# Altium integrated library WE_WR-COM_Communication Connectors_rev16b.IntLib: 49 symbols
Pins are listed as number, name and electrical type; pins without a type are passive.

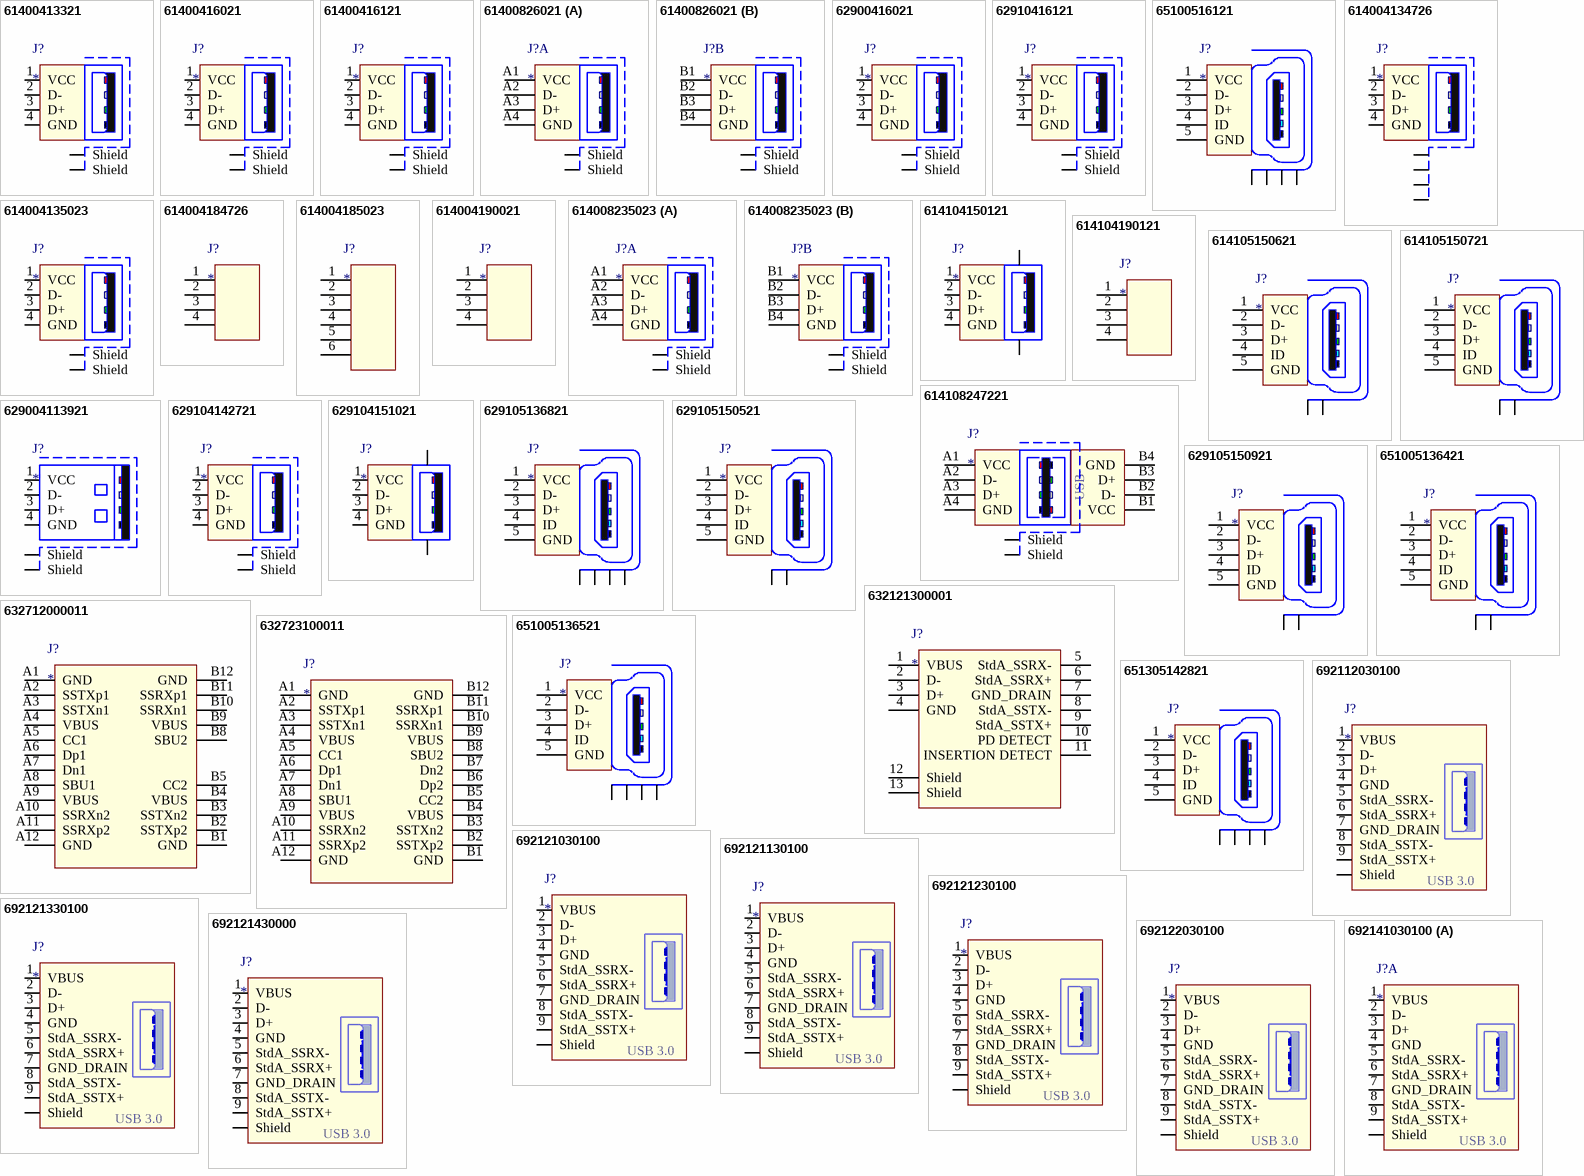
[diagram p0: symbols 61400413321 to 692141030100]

## 61400413321
designator J?
WR-COM USB Vertical Type B; Manufacturer: Würth Elektronik eiSos GmbH; partNo: 61400413321; ComponentLink1 Description: Manufacturer; ComponentLink2 Description: Datasheet; NoPins: 4
footprint 61400413321 (F Str 04p Btype vertical)
pins: 1 VCC, 2 D-, 3 D+, 4 GND, Z1 Shield, Z2 Shield

## 61400416021
designator J?
WR-COM USB RA Type A; Manufacturer: Würth Elektronik eiSos GmbH; partNo: 61400416021; ComponentLink1 Description: Manufacturer; ComponentLink2 Description: Datasheet; NoPins: 4
footprint 61400416021
pins: 1 VCC, 2 D-, 3 D+, 4 GND, Z1 Shield, Z2 Shield

## 61400416121
designator J?
WR-COM Horizontal USB Type B; Manufacturer: Würth Elektronik eiSos GmbH; partNo: 61400416121; ComponentLink1 Description: Manufacturer; ComponentLink2 Description: Datasheet; NoPins: 4
footprint 61400416121
pins: 1 VCC, 2 D-, 3 D+, 4 GND, Z1 Shield, Z2 Shield

## 61400826021
designator J?
WR-COM USB Type A Dual Stacked; Manufacturer: Würth Elektronik eiSos GmbH; partNo: 61400826021; ComponentLink1 Description: Manufacturer; ComponentLink2 Description: Datasheet; NoPins: 8
footprint 61400826021 (2 x 4 pins)
part A pins: A1 VCC, A2 D-, A3 D+, A4 GND, Z1 Shield, Z2 Shield
part B pins: B1 VCC, B2 D-, B3 D+, B4 GND, Z3 Shield, Z4 Shield

## 62900416021
designator J?
WR-COM USB SMT Type A; Manufacturer: Würth Elektronik eiSos GmbH; partNo: 62900416021; ComponentLink1 Description: Manufacturer; ComponentLink2 Description: Datasheet; NoPins: 4
footprint 62900416021
pins: 1 VCC, 2 D-, 3 D+, 4 GND, Z1 Shield, Z2 Shield

## 62910416121
designator J?
WR-COM USB Type B SMT T&R packaging; Manufacturer: Würth Elektronik eiSos GmbH; partNo: 62910416121; ComponentLink1 Description: Manufacturer; ComponentLink2 Description: Datasheet; NoPins: 4
footprint 62910416121 (4 pins)
pins: 1 VCC, 2 D-, 3 D+, 4 GND, Z1 Shield, Z2 Shield

## 65100516121
designator J?
WR-COM Mini USB SMT Type B 5 Contacts; Manufacturer: Würth Elektronik eiSos GmbH; partNo: 65100516121; ComponentLink1 Description: Manufacturer; ComponentLink2 Description: Datasheet; NoPins: 5
footprint 65100516121
pins: 1 VCC, 2 D-, 3 D+, 4 ID, 5 GND, Z1 Shield, Z2 Shield, Z3 Shield, Z4 Shield

## 614004134726
designator J?
WR-COM USB Type A Up-Right; Manufacturer: Würth Elektronik eiSos GmbH; partNo: 614004134726; ComponentLink1 Description: Manufacturer; ComponentLink2 Description: Datasheet; NoPins: 4
footprint 614004134726
pins: 1 VCC, 2 D-, 3 D+, 4 GND, Z1 Shield, Z2 Shield, Z3 Shield, Z4 Shield

## 614004135023
designator J?
WR-COM USB Type A Vertical; Manufacturer: Würth Elektronik eiSos GmbH; partNo: 614004135023; ComponentLink1 Description: Manufacturer; ComponentLink2 Description: Datasheet; NoPins: 4
footprint 614004135023
pins: 1 VCC, 2 D-, 3 D+, 4 GND, Z1 Shield, Z2 Shield

## 614004184726
designator J?
WR-COM_USB_Type A Up Right THT; Manufacturer: Wurth Elektronik; partNo: 614004184726; ComponentLink1 Description: Manufacturer; ComponentLink2 Description: Datasheet; NoPins: 4
footprint 614004184726 (Type A Up Right THT - Short Type)
pins: 1, 2, 3, 4

## 614004185023
designator J?
WR-COM_USB_Type A Vertical THT; Manufacturer: Wurth Elektronik; partNo: 614004185023; ComponentLink1 Description: Manufacturer; ComponentLink2 Description: Datasheet; NoPins: 6
footprint 614004185023 (Type A Vertical THT - with Clips - Short Type)
pins: 1, 2, 3, 4, 5, 6

## 614004190021
designator J?
WR-COM_USB_Type A Horizontal THT; Manufacturer: Wurth Elektronik; partNo: 614004190021; ComponentLink1 Description: Manufacturer; ComponentLink2 Description: Datasheet; NoPins: 4
footprint 614004190021 (Type A Horizontal THT)
pins: 1, 2, 3, 4

## 614008235023
designator J?
WR-COM Dual USB Type A Vertical; Manufacturer: Würth Elektronik eiSos GmbH; partNo: 614008235023; ComponentLink1 Description: Manufacturer; ComponentLink2 Description: Datasheet; NoPins: 8
footprint 614008235023 (2 x 4 pins)
part A pins: A1 VCC, A2 D-, A3 D+, A4 GND, Z1 Shield, Z2 Shield
part B pins: B1 VCC, B2 D-, B3 D+, B4 GND, Z1 Shield, Z2 Shield

## 614104150121
designator J?
WR-COM_USB_Type A_Reverse Horizontal_THT; Manufacturer: Würth Elektronik eiSos GmbH; partNo: 614104150121; ComponentLink1 Description: Manufacturer; ComponentLink2 Description: Datasheet; NoPins: 4
footprint 614104150121 (WR-COM_USB_Type A_Reverse Horizontal_THT Type A Reverse Horizontal THT - with Clips - Slim type for PCB thickness 1.20mm)
pins: 1 VCC, 2 D-, 3 D+, 4 GND, Z1 Shield, Z2 Shield

## 614104190121
designator J?
WR-COM_USB_Type A Horizontal THT; Manufacturer: Wurth Elektronik; partNo: 614104190121; ComponentLink1 Description: Manufacturer; ComponentLink2 Description: Datasheet; NoPins: 4
footprint 614104190121 (Type A Horizontal THT - Short Type)
pins: 1, 2, 3, 4

## 614105150621
designator J?
WR-COM_USB_Micro Type AB_Vertical_THT; Manufacturer: Würth Elektronik eiSos GmbH; partNo: 614105150621; ComponentLink1 Description: Manufacturer; ComponentLink2 Description: Datasheet; NoPins: 5
footprint 614105150621
pins: 1 VCC, 2 D-, 3 D+, 4 ID, 5 GND, Z1 Shield, Z2 Shield

## 614105150721
designator J?
WR-COM_USB_Micro Type B_Vertical_THT; Manufacturer: Würth Elektronik eiSos GmbH; partNo: 614105150721; ComponentLink1 Description: Manufacturer; ComponentLink2 Description: Datasheet; NoPins: 5
footprint 614105150721
pins: 1 VCC, 2 D-, 3 D+, 4 ID, 5 GND, Z1 Shield, Z2 Shield

## 614108247221
designator J?
WR-COM USB 2.0_Reversible_Type A_Horizontal_THT; Manufacturer: Würth Elektronik eiSos GmbH; partNo: 614108247221; ComponentLink1 Description: Manufacturer; ComponentLink2 Description: Datasheet; NoPins: 8
footprint 614108247221 (WR-COM USB_Reversible_Type A_Horizontal_THT_Black)
pins: A1 VCC, A2 D-, A3 D+, A4 GND, B1 VCC, B2 D-, B3 D+, B4 GND, Z1 Shield, Z2 Shield

## 629004113921
designator J?
WR-COM USB Type A SMT with Clip; Manufacturer: Würth Elektronik eiSos GmbH; partNo: 629004113921; ComponentLink1 Description: Manufacturer; ComponentLink2 Description: Datasheet; NoPins: 4
footprint 629004113921
pins: 1 VCC, 2 D-, 3 D+, 4 GND, Z1 Shield, Z2 Shield

## 629104142721
designator J?
WR-COM USB Type B SMT T&R packaging; Manufacturer: Würth Elektronik eiSos GmbH; partNo: 629104142721; ComponentLink1 Description: Manufacturer; ComponentLink2 Description: Datasheet; NoPins: 4
footprint 629104142721
pins: 1 VCC, 2 D-, 3 D+, 4 GND, Z1 Shield, Z2 Shield

## 629104151021
designator J?
WR-COM_USB_Type A_Horizontal_SMT; Manufacturer: Würth Elektronik eiSos GmbH; partNo: 629104151021; ComponentLink1 Description: Manufacturer; ComponentLink2 Description: Datasheet; NoPins: 4
footprint 629104151021
pins: 1 VCC, 2 D-, 3 D+, 4 GND, Z1 Shield, Z2 Shield

## 629105136821
designator J?
WR-COM Micro USB SMT Type B; Manufacturer: Würth Elektronik eiSos GmbH; partNo: 629105136821; ComponentLink1 Description: Manufacturer; ComponentLink2 Description: Datasheet; NoPins: 5
footprint 629105136821
pins: 1 VCC, 2 D-, 3 D+, 4 ID, 5 GND, Z1 Shield, Z2 Shield, Z3 Shield, Z4 Shield

## 629105150521
designator J?
WR-COM_USB_Micro Type B_Horizontal_SMT; Manufacturer: Würth Elektronik eiSos GmbH; partNo: 629105150521; ComponentLink1 Description: Manufacturer; ComponentLink2 Description: Datasheet; NoPins: 5
footprint 629105150521
pins: 1 VCC, 2 D-, 3 D+, 4 ID, 5 GND, Z1 Shield, Z2 Shield

## 629105150921
designator J?
WR-COM_USB_Micro Type AB_Horizontal_SMT; Manufacturer: Würth Elektronik eiSos GmbH; partNo: 629105150921; ComponentLink1 Description: Manufacturer; ComponentLink2 Description: Datasheet; NoPins: 5
footprint 629105150921 (WR-COM_USB_Micro Type AB_Horizontal_SMT Micro Type AB Horizontal SMT - with Pegs - T&R Packaging)
pins: 1 VCC, 2 D-, 3 D+, 4 ID, 5 GND, Z1 Shield, Z2 Shield

## 632121300001
designator J?
WR-COM_USB_USB 3.1_Type A_Horizontal_THT; Manufacturer: Wurth Elektronik; partNo: 632121300001; ComponentLink1 Description: Manufacturer; ComponentLink2 Description: Datasheet; NoPins: 13
footprint 632121300001 (USB 3.1_Type A_Horizontal_THT)
pins: 1 VBUS, 2 D-, 3 D+, 4 GND, 5 StdA_SSRX-, 6 StdA_SSRX+, 7 GND_DRAIN, 8 StdA_SSTX-, 9 StdA_SSTX+, 10 PD DETECT, 11 INSERTION DETECT, 12 Shield, 13 Shield

## 632712000011
designator J?
WR-COM_USB_Type C Plug Horizontal SMT; Manufacturer: Wurth Elektronik; partNo: 632712000011; ComponentLink1 Description: Manufacturer; ComponentLink2 Description: Datasheet; NoPins: 22
footprint 632712000011 (Type C Plug Horizontal SMT)
pins: A1 GND, A2 SSTXp1, A3 SSTXn1, A4 VBUS, A5 CC1, A6 Dp1, A7 Dn1, A8 SBU1, A9 VBUS, A10 SSRXn2, A11 SSRXp2, A12 GND, B1 GND, B2 SSTXp2, B3 SSTXn2, B4 VBUS, B5 CC2, B8 SBU2, B9 VBUS, B10 SSRXn1, B11 SSRXp1, B12 GND

## 632723100011
designator J?
WR-COM_USB_USB 3.1_Type C_Horizontal_THT/SMT; Manufacturer: Wurth Elektronik; partNo: 632723100011; ComponentLink1 Description: Manufacturer; ComponentLink2 Description: Datasheet; NoPins: 24
footprint 632723100011 (USB 3.1_Type C_Horizontal_THT/SMT_1.0mm)
pins: A1 GND, A2 SSTXp1, A3 SSTXn1, A4 VBUS, A5 CC1, A6 Dp1, A7 Dn1, A8 SBU1, A9 VBUS, A10 SSRXn2, A11 SSRXp2, A12 GND, B1 GND, B2 SSTXp2, B3 SSTXn2, B4 VBUS, B5 CC2, B6 Dp2, B7 Dn2, B8 SBU2, B9 VBUS, B10 SSRXn1, B11 SSRXp1, B12 GND

## 651005136421
designator J?
WR-COM Mini USB Vertical TH Type B 5 Contacts; Manufacturer: Würth Elektronik eiSos GmbH; partNo: 651005136421; ComponentLink1 Description: Manufacturer; ComponentLink2 Description: Datasheet; NoPins: 5
footprint 651005136421
pins: 1 VCC, 2 D-, 3 D+, 4 ID, 5 GND, Z1 Shield, Z2 Shield

## 651005136521
designator J?
WR-COM Mini USB Horizontal TH Type B 5 Contacts; Manufacturer: Würth Elektronik eiSos GmbH; partNo: 651005136521; ComponentLink1 Description: Manufacturer; ComponentLink2 Description: Datasheet; NoPins: 5
footprint 651005136521
pins: 1 VCC, 2 D-, 3 D+, 4 ID, 5 GND, Z1 Shield, Z2 Shield, Z3 Shield, Z4 Shield

## 651305142821
designator J?
WR-COM Mini USB SMT Type AB 5 Contacts; Manufacturer: Würth Elektronik eiSos GmbH; partNo: 651305142821; ComponentLink1 Description: Manufacturer; ComponentLink2 Description: Datasheet; NoPins: 5
footprint 651305142821
pins: 1 VCC, 2 D-, 3 D+, 4 ID, 5 GND, Z1 Shield, Z2 Shield, Z3 Shield, Z4 Shield

## 692112030100
designator J?
WR-COM USB 3.0 Horizontal Plug Type A; Manufacturer: Würth Elektronik eiSos GmbH; partNo: 692112030100; ComponentLink1 Description: Manufacturer; ComponentLink2 Description: Datasheet; NoPins: 9
footprint 692112030100
pins: 1 VBUS, 2 D-, 3 D+, 4 GND, 5 StdA_SSRX-, 6 StdA_SSRX+, 7 GND_DRAIN, 8 StdA_SSTX-, 9 StdA_SSTX+, Z1 Shield

## 692121030100
designator J?
WR-COM USB 3.0 Horizontal Type A; Manufacturer: Würth Elektronik eiSos GmbH; partNo: 692121030100; ComponentLink1 Description: Manufacturer; ComponentLink2 Description: Datasheet; NoPins: 9
footprint 692121030100
pins: 1 VBUS, 2 D-, 3 D+, 4 GND, 5 StdA_SSRX-, 6 StdA_SSRX+, 7 GND_DRAIN, 8 StdA_SSTX-, 9 StdA_SSTX+, Z1 Shield

## 692121130100
designator J?
WR-COM USB 3.0 Horizontal Type A; Manufacturer: Würth Elektronik eiSos GmbH; partNo: 692121130100; ComponentLink1 Description: Manufacturer; ComponentLink2 Description: Datasheet; NoPins: 9
footprint 692121130100
pins: 1 VBUS, 2 D-, 3 D+, 4 GND, 5 StdA_SSRX-, 6 StdA_SSRX+, 7 GND_DRAIN, 8 StdA_SSTX-, 9 StdA_SSTX+, Z1 Shield

## 692121230100
designator J?
WR-COM USB 3.0 Horizontal Type A; Manufacturer: Würth Elektronik eiSos GmbH; partNo: 692121230100; ComponentLink1 Description: Manufacturer; ComponentLink2 Description: Datasheet; NoPins: 9
footprint 692121230100
pins: 1 VBUS, 2 D-, 3 D+, 4 GND, 5 StdA_SSRX-, 6 StdA_SSRX+, 7 GND_DRAIN, 8 StdA_SSTX-, 9 StdA_SSTX+, Z1 Shield

## 692121330100
designator J?
WR-COM USB 3.0 Horizontal Type A; Manufacturer: Würth Elektronik eiSos GmbH; partNo: 692121330100; ComponentLink1 Description: Manufacturer; ComponentLink2 Description: Datasheet; NoPins: 9
footprint 692121330100
pins: 1 VBUS, 2 D-, 3 D+, 4 GND, 5 StdA_SSRX-, 6 StdA_SSRX+, 7 GND_DRAIN, 8 StdA_SSTX-, 9 StdA_SSTX+, Z1 Shield

## 692121430000
designator J?
WR-COM USB 3.0 Vertical Type A; Manufacturer: Würth Elektronik eiSos GmbH; partNo: 692121430000; ComponentLink1 Description: Manufacturer; ComponentLink2 Description: Datasheet; NoPins: 9
footprint 692121430000
pins: 1 VBUS, 2 D-, 3 D+, 4 GND, 5 StdA_SSRX-, 6 StdA_SSRX+, 7 GND_DRAIN, 8 StdA_SSTX-, 9 StdA_SSTX+, Z1 Shield

## 692122030100
designator J?
WR-COM USB 3.0 Horizontal Type A; Manufacturer: Würth Elektronik eiSos GmbH; partNo: 692122030100; ComponentLink1 Description: Manufacturer; ComponentLink2 Description: Datasheet; NoPins: 9
footprint 692122030100
pins: 1 VBUS, 2 D-, 3 D+, 4 GND, 5 StdA_SSRX-, 6 StdA_SSRX+, 7 GND_DRAIN, 8 StdA_SSTX-, 9 StdA_SSTX+, Z1 Shield

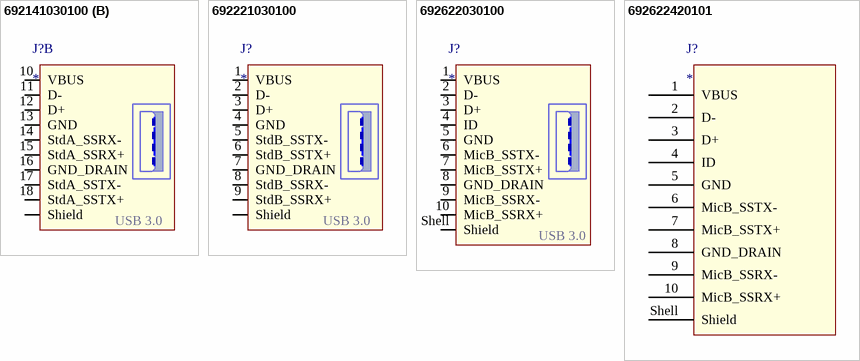
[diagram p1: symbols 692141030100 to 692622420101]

## 692141030100
designator J?
WR-COM USB 3.0 Horizontal Type A; Manufacturer: Würth Elektronik eiSos GmbH; partNo: 692141030100; ComponentLink1 Description: Manufacturer; ComponentLink2 Description: Datasheet; NoPins: 18
footprint 692141030100
part A pins: 1 VBUS, 2 D-, 3 D+, 4 GND, 5 StdA_SSRX-, 6 StdA_SSRX+, 7 GND_DRAIN, 8 StdA_SSTX-, 9 StdA_SSTX+, Z1 Shield
part B pins: 10 VBUS, 11 D-, 12 D+, 13 GND, 14 StdA_SSRX-, 15 StdA_SSRX+, 16 GND_DRAIN, 17 StdA_SSTX-, 18 StdA_SSTX+, Z1 Shield

## 692221030100
designator J?
WR-COM USB 3.0 Horizontal Type B; Manufacturer: Würth Elektronik eiSos GmbH; partNo: 692221030100; ComponentLink1 Description: Manufacturer; ComponentLink2 Description: Datasheet; NoPins: 9
footprint 692221030100
pins: 1 VBUS, 2 D-, 3 D+, 4 GND, 5 StdB_SSTX-, 6 StdB_SSTX+, 7 GND_DRAIN, 8 StdB_SSRX-, 9 StdB_SSRX+, Z1 Shield

## 692622030100
designator J?
WR-COM USB 3.0 Horizontal Micro B; Manufacturer: Würth Elektronik eiSos GmbH; partNo: 692622030100; ComponentLink1 Description: Manufacturer; ComponentLink2 Description: Datasheet; NoPins: 10
footprint 692622030100
pins: 1 VBUS, 2 D-, 3 D+, 4 ID, 5 GND, 6 MicB_SSTX-, 7 MicB_SSTX+, 8 GND_DRAIN, 9 MicB_SSRX-, 10 MicB_SSRX+, Shell Shield

## 692622420101
designator J?
WR-COM_USB_USB 3.1_Micro Type B Vertical SMT; Manufacturer: Wurth Elektronik; partNo: 692622420101; ComponentLink1 Description: Manufacturer; ComponentLink2 Description: Datasheet; NoPins: 10
footprint 692622420101 (Micro Type B Vertical SMT - with Pads & positionning peg)
pins: 1 VBUS, 2 D-, 3 D+, 4 ID, 5 GND, 6 MicB_SSTX-, 7 MicB_SSTX+, 8 GND_DRAIN, 9 MicB_SSRX-, 10 MicB_SSRX+, Shell Shield


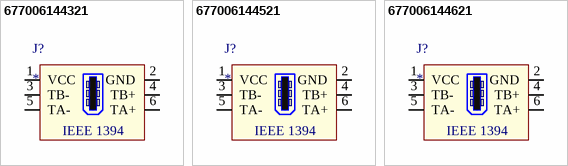
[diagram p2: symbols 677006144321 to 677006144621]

## 677006144321
designator J?
WR-COM IEEE 1394 connector; Manufacturer: Würth Elektronik eiSos GmbH; partNo: 677006144321; ComponentLink1 Description: Manufacturer; ComponentLink2 Description: Datasheet; NoPins: 6
footprint 677006144321
pins: 1 VCC, 2 GND, 3 TB-, 4 TB+, 5 TA-, 6 TA+

## 677006144521
designator J?
WR-COM IEEE 1394 connector; Manufacturer: Würth Elektronik eiSos GmbH; partNo: 677006144521; ComponentLink1 Description: Manufacturer; ComponentLink2 Description: Datasheet; NoPins: 6
footprint 677006144521 (Female PCB connector Horizontal TH)
pins: 1 VCC, 2 GND, 3 TB-, 4 TB+, 5 TA-, 6 TA+

## 677006144621
designator J?
WR-COM IEEE 1394 connector; Manufacturer: Würth Elektronik eiSos GmbH; partNo: 677006144621; ComponentLink1 Description: Manufacturer; ComponentLink2 Description: Datasheet; NoPins: 6
footprint 677006144621
pins: 1 VCC, 2 GND, 3 TB-, 4 TB+, 5 TA-, 6 TA+


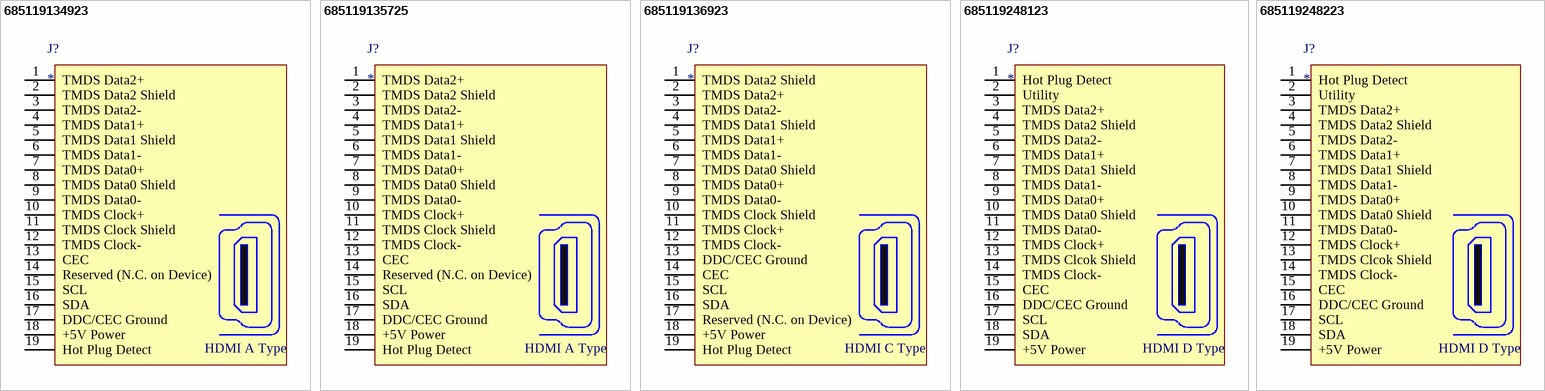
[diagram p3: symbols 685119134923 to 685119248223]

## 685119134923
designator J?
WR-COM HDMI SMT Horizontal; Manufacturer: Wurth Elektronik; partNo: 685119134923; ComponentLink1 Description: Manufacturer; ComponentLink2 Description: Datasheet; NoPins: 19
footprint 685119134923 (19 pins)
pins: 1 TMDS Data2+, 2 TMDS Data2 Shield, 3 TMDS Data2-, 4 TMDS Data1+, 5 TMDS Data1 Shield, 6 TMDS Data1-, 7 TMDS Data0+, 8 TMDS Data0 Shield, 9 TMDS Data0-, 10 TMDS Clock+, 11 TMDS Clock Shield, 12 TMDS Clock-, 13 CEC, 14 Reserved (N.C. on Device), 15 SCL, 16 SDA, 17 DDC/CEC Ground, 18 +5V Power, 19 Hot Plug Detect

## 685119135725
designator J?
WR-COM HDMI SMT Horizontal with M3 screw; Manufacturer: Wurth Elektronik; partNo: 685119135725; ComponentLink1 Description: Manufacturer; ComponentLink2 Description: Datasheet; NoPins: 19
footprint 685119135725 (19p + M3 flange)
pins: 1 TMDS Data2+, 2 TMDS Data2 Shield, 3 TMDS Data2-, 4 TMDS Data1+, 5 TMDS Data1 Shield, 6 TMDS Data1-, 7 TMDS Data0+, 8 TMDS Data0 Shield, 9 TMDS Data0-, 10 TMDS Clock+, 11 TMDS Clock Shield, 12 TMDS Clock-, 13 CEC, 14 Reserved (N.C. on Device), 15 SCL, 16 SDA, 17 DDC/CEC Ground, 18 +5V Power, 19 Hot Plug Detect

## 685119136923
designator J?
WR-COM Mini HDMI SMT Horizontal; Manufacturer: Wurth Elektronik; partNo: 685119136923; ComponentLink1 Description: Manufacturer; ComponentLink2 Description: Datasheet; NoPins: 19
footprint 685119136923 (19p)
pins: 1 TMDS Data2 Shield, 2 TMDS Data2+, 3 TMDS Data2-, 4 TMDS Data1 Shield, 5 TMDS Data1+, 6 TMDS Data1-, 7 TMDS Data0 Shield, 8 TMDS Data0+, 9 TMDS Data0-, 10 TMDS Clock Shield, 11 TMDS Clock+, 12 TMDS Clock-, 13 DDC/CEC Ground, 14 CEC, 15 SCL, 16 SDA, 17 Reserved (N.C. on Device), 18 +5V Power, 19 Hot Plug Detect

## 685119248123
designator J?
WR-COM Micro HDMI Horizontal; Manufacturer: Wurth Elektronik; partNo: 685119248123; ComponentLink1 Description: Manufacturer; ComponentLink2 Description: Datasheet; NoPins: 19
footprint 685119248123 (Receptacle THT shell tabs)
pins: 1 Hot Plug Detect, 2 Utility, 3 TMDS Data2+, 4 TMDS Data2 Shield, 5 TMDS Data2-, 6 TMDS Data1+, 7 TMDS Data1 Shield, 8 TMDS Data1-, 9 TMDS Data0+, 10 TMDS Data0 Shield, 11 TMDS Data0-, 12 TMDS Clock+, 13 TMDS Clcok Shield, 14 TMDS Clock-, 15 CEC, 16 DDC/CEC Ground, 17 SCL, 18 SDA, 19 +5V Power

## 685119248223
designator J?
WR-COM Micro HDMI Horizontal SMT Hybrid Mount; Manufacturer: Wurth Elektronik; partNo: 685119248223; ComponentLink1 Description: Manufacturer; ComponentLink2 Description: Datasheet; NoPins: 19
footprint 685119248223 (Receptacle Hybird Mount consist of Vertical and Horizontal Type shell tabs)
pins: 1 Hot Plug Detect, 2 Utility, 3 TMDS Data2+, 4 TMDS Data2 Shield, 5 TMDS Data2-, 6 TMDS Data1+, 7 TMDS Data1 Shield, 8 TMDS Data1-, 9 TMDS Data0+, 10 TMDS Data0 Shield, 11 TMDS Data0-, 12 TMDS Clock+, 13 TMDS Clcok Shield, 14 TMDS Clock-, 15 CEC, 16 DDC/CEC Ground, 17 SCL, 18 SDA, 19 +5V Power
